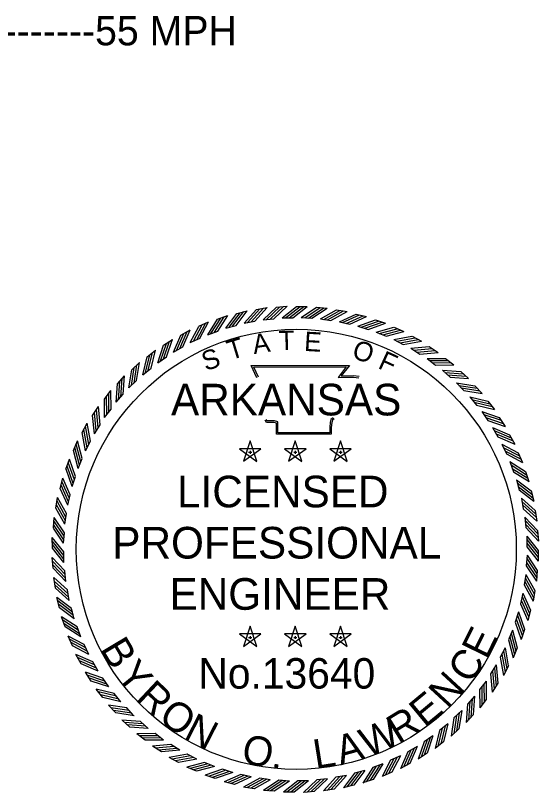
# Model space of a CAD drawing. Extents: x 171 to 3403, y 68 to 2102.
# Drawn here: x 2978.6 to 3245.8, y 313.8 to 710.8 of the extents above; entities that cross this region are included whole.
import ezdxf

# ---------------------------------------------------------------- set-up
doc = ezdxf.new("R2010")
doc.units = 0
for name, color, linetype in [('1', 7, 'Continuous'), ('G-ANNO-NPLT', 7, 'Continuous'), ('STAMP', 7, 'Continuous')]:
    doc.layers.add(name, color=color, linetype=linetype)

msp = doc.modelspace()

# ---------------------------------------------------------------- linework, layer by layer
at = {"layer": 'G-ANNO-NPLT'}
msp.add_circle((3122.09, 438.03), 112.43, dxfattribs=at)
at = {"layer": 'STAMP'}
for p, q in [((3091.74, 558.52), (3097, 559.91)), ((3101.79, 560.58), (3107.15, 561.52)), ((3111.98, 561.8), (3117.4, 562.29)), ((3122.28, 562.1), (3127.72, 562.1)), ((3132.48, 561.69), (3137.9, 561.29)), ((3142.65, 560.37), (3148.03, 559.52)), ((3081.89, 555.65), (3087.02, 557.46)), ((3105.11, 555.35), (3110.54, 555.85)), ((3114.86, 556.31), (3120.31, 556.31)), ((3124.64, 556.46), (3130.08, 556.06)), ((3134.41, 555.8), (3139.8, 554.96)), ((3152.68, 558.21), (3157.97, 556.93)), ((3072.32, 551.97), (3077.28, 554.2)), ((3086.03, 551.03), (3091.3, 552.42)), ((3095.48, 553.59), (3100.85, 554.53)), ((3144.09, 554.34), (3149.39, 553.05)), ((3153.62, 552.09), (3158.8, 550.36)), ((3162.5, 555.24), (3167.66, 553.52)), ((3063.08, 547.51), (3067.84, 550.14)), ((3076.82, 547.71), (3081.96, 549.53)), ((3162.93, 549.05), (3167.94, 546.91)), ((3172.03, 551.46), (3177.04, 549.32)), ((3054.24, 542.3), (3058.77, 545.32)), ((3067.92, 543.64), (3072.89, 545.88)), ((3171.95, 545.26), (3176.78, 542.71)), ((3181.23, 546.91), (3186.04, 544.36)), ((3059.38, 538.85), (3064.15, 541.49)), ((3180.64, 540.74), (3185.23, 537.8)), ((3190.01, 541.61), (3194.6, 538.67)), ((3045.86, 536.38), (3050.12, 539.77)), ((3051.27, 533.36), (3055.81, 536.39)), ((3038, 529.79), (3041.97, 533.52)), ((3188.91, 535.51), (3193.25, 532.2)), ((3198.33, 535.61), (3202.66, 532.3)), ((3043.64, 527.23), (3047.91, 530.62)), ((3196.73, 529.62), (3200.78, 525.96)), ((3206.13, 528.94), (3210.16, 525.29)), ((3030.7, 522.58), (3034.35, 526.61)), ((3036.54, 520.49), (3040.52, 524.22)), ((3204.04, 523.1), (3207.77, 519.12)), ((3213.34, 521.64), (3217.07, 517.67)), ((3024.03, 514.78), (3027.34, 519.11)), ((3030.02, 513.18), (3033.68, 517.23)), ((3210.78, 516), (3214.17, 511.73)), ((3219.93, 513.78), (3223.32, 509.52)), ((3018.03, 506.46), (3020.96, 511.05)), ((3024.13, 505.36), (3027.44, 509.7)), ((3216.91, 508.37), (3219.94, 503.83)), ((3225.85, 505.4), (3228.87, 500.87)), ((3012.73, 497.68), (3015.28, 502.49)), ((3018.9, 497.09), (3021.84, 501.68)), ((3222.4, 500.26), (3225.04, 495.49)), ((3231.06, 496.56), (3233.69, 491.8)), ((3008.18, 488.48), (3010.32, 493.49)), ((3014.38, 488.4), (3016.93, 493.23)), ((3098.5, 493.43), (3095.09, 482.99)), ((3101.89, 482.99), (3098.51, 493.44)), ((3121.58, 493.43), (3118.18, 482.99)), ((3124.98, 482.99), (3121.59, 493.44)), ((3144.67, 493.43), (3141.26, 482.99)), ((3148.06, 482.99), (3144.68, 493.44)), ((3103.99, 489.44), (3093, 489.46)), ((3093.01, 489.44), (3101.89, 482.98)), ((3095.11, 482.99), (3104, 489.44)), ((3127.07, 489.44), (3116.09, 489.46)), ((3116.1, 489.44), (3124.98, 482.98)), ((3118.19, 482.99), (3127.09, 489.44)), ((3150.16, 489.44), (3139.17, 489.46)), ((3139.18, 489.44), (3148.06, 482.98)), ((3141.28, 482.99), (3150.17, 489.44)), ((3227.19, 491.72), (3229.43, 486.75)), ((3010.59, 479.38), (3012.73, 484.39)), ((3097.72, 487.69), (3099.35, 487.69)), ((3098.51, 488.28), (3098.51, 486.9)), ((3120.8, 487.69), (3122.44, 487.69)), ((3121.59, 488.28), (3121.59, 486.9)), ((3143.89, 487.69), (3145.52, 487.69)), ((3144.68, 488.28), (3144.68, 486.9)), ((3235.52, 487.32), (3237.75, 482.36)), ((3004.4, 478.95), (3006.12, 484.11)), ((3231.26, 482.82), (3233.08, 477.68)), ((3239.2, 477.75), (3241.01, 472.62)), ((3001.43, 469.13), (3002.71, 474.42)), ((3007.55, 470.07), (3009.28, 475.25)), ((3234.58, 473.61), (3235.97, 468.33)), ((2999.27, 459.1), (3000.12, 464.48)), ((3005.3, 460.54), (3006.59, 465.84)), ((3242.07, 467.9), (3243.46, 462.64)), ((3237.14, 464.16), (3238.08, 458.79)), ((3244.13, 457.85), (3245.07, 452.49)), ((2997.95, 448.93), (2998.35, 454.35)), ((3003.84, 450.86), (3004.68, 456.25)), ((3238.9, 454.53), (3239.4, 449.1)), ((3003.18, 441.09), (3003.58, 446.53)), ((3239.86, 444.78), (3239.91, 439.33)), ((3245.35, 447.66), (3245.84, 442.24)), ((2997.47, 438.68), (2997.42, 444.12)), ((3003.33, 431.3), (3003.28, 436.76)), ((3245.72, 437.41), (3245.77, 431.97)), ((2997.84, 428.43), (2997.35, 433.85)), ((3240.01, 435), (3239.61, 429.56)), ((3004.29, 421.56), (3003.79, 426.99)), ((3239.35, 425.23), (3238.51, 419.84)), ((3245.24, 427.16), (3244.84, 421.74)), ((2999.06, 418.24), (2998.12, 423.6)), ((3006.05, 411.93), (3005.11, 417.3)), ((3243.92, 416.99), (3243.07, 411.61)), ((3001.12, 408.19), (2999.73, 413.45)), ((3237.89, 415.55), (3236.6, 410.25)), ((3008.61, 402.48), (3007.22, 407.75)), ((3235.64, 406.02), (3233.91, 400.84)), ((3241.76, 406.96), (3240.48, 401.67)), ((3003.99, 398.34), (3002.18, 403.47)), ((3011.93, 393.27), (3010.11, 398.41)), ((3098.5, 398.78), (3095.09, 388.34)), ((3101.89, 388.34), (3098.51, 398.79)), ((3121.58, 398.78), (3118.18, 388.34)), ((3124.98, 388.34), (3121.59, 398.79)), ((3144.67, 398.78), (3141.26, 388.34)), ((3148.06, 388.34), (3144.68, 398.79)), ((3238.79, 397.14), (3237.07, 391.98)), ((3007.67, 388.77), (3005.44, 393.73)), ((3103.99, 394.79), (3093, 394.8)), ((3093.01, 394.79), (3101.89, 388.33)), ((3095.11, 388.34), (3104, 394.79)), ((3097.72, 393.04), (3099.35, 393.04)), ((3098.51, 393.63), (3098.51, 392.25)), ((3127.07, 394.79), (3116.09, 394.8)), ((3116.1, 394.79), (3124.98, 388.33)), ((3118.19, 388.34), (3127.09, 394.79)), ((3120.8, 393.04), (3122.44, 393.04)), ((3121.59, 393.63), (3121.59, 392.25)), ((3150.16, 394.79), (3139.17, 394.8)), ((3139.18, 394.79), (3148.06, 388.33)), ((3141.28, 388.34), (3150.17, 394.79)), ((3143.89, 393.04), (3145.52, 393.04)), ((3144.68, 393.63), (3144.68, 392.25)), ((3232.6, 396.71), (3230.46, 391.7)), ((3016, 384.37), (3013.76, 389.34)), ((3228.81, 387.69), (3226.26, 382.86)), ((3235.01, 387.61), (3232.87, 382.6)), ((3012.13, 379.53), (3009.5, 384.29)), ((3020.79, 375.83), (3018.15, 380.6)), ((3224.29, 379), (3221.35, 374.41)), ((3230.46, 378.41), (3227.91, 373.6)), ((3017.34, 370.69), (3014.32, 375.21)), ((3026.28, 367.72), (3023.25, 372.26)), ((3219.06, 370.72), (3215.75, 366.39)), ((3225.16, 369.63), (3222.22, 365.04)), ((3023.26, 362.31), (3019.87, 366.57)), ((3032.41, 360.09), (3029.02, 364.36)), ((3213.17, 362.91), (3209.51, 358.86)), ((3219.16, 361.31), (3215.85, 356.98)), ((3029.85, 354.45), (3026.12, 358.41)), ((3039.15, 352.99), (3035.42, 356.97)), ((3206.65, 355.6), (3202.67, 351.87)), ((3212.49, 353.51), (3208.84, 349.48)), ((3037.06, 347.15), (3033.03, 350.8)), ((3046.46, 346.47), (3042.41, 350.13)), ((3199.55, 348.86), (3195.28, 345.47)), ((3205.19, 346.3), (3201.22, 342.57)), ((3044.86, 340.48), (3040.53, 343.79)), ((3054.27, 340.58), (3049.94, 343.89)), ((3191.92, 342.73), (3187.38, 339.7)), ((3062.55, 335.35), (3057.96, 338.29)), ((3197.33, 339.71), (3193.07, 336.32)), ((3053.18, 334.48), (3048.59, 337.41)), ((3183.81, 337.24), (3179.04, 334.6)), ((3188.95, 333.79), (3184.42, 330.77)), ((3061.96, 329.18), (3057.15, 331.73)), ((3071.24, 330.83), (3066.41, 333.38)), ((3175.27, 332.45), (3170.3, 330.21)), ((3071.16, 324.63), (3066.15, 326.77)), ((3080.26, 327.04), (3075.25, 329.18)), ((3089.57, 324), (3084.39, 325.72)), ((3166.37, 328.38), (3161.23, 326.56)), ((3180.11, 328.58), (3175.35, 325.95)), ((3080.69, 320.85), (3075.53, 322.57)), ((3099.1, 321.75), (3093.8, 323.04)), ((3147.71, 322.5), (3142.34, 321.56)), ((3157.16, 325.06), (3151.88, 323.67)), ((3170.87, 324.12), (3165.91, 321.89)), ((3090.51, 317.88), (3085.22, 319.16)), ((3108.78, 320.29), (3103.39, 321.13)), ((3118.55, 319.63), (3113.11, 320.03)), ((3128.33, 319.78), (3122.88, 319.73)), ((3138.08, 320.74), (3132.65, 320.24)), ((3161.3, 320.44), (3156.17, 318.63)), ((3100.54, 315.72), (3095.16, 316.57)), ((3110.71, 314.4), (3105.29, 314.8)), ((3120.96, 313.92), (3115.52, 313.87)), ((3131.21, 314.29), (3125.79, 313.79)), ((3141.4, 315.51), (3136.04, 314.57)), ((3151.45, 317.57), (3146.19, 316.18))]:
    msp.add_line(p, q, dxfattribs=at)
for points in [[(3091.3, 552.42), (3097.01, 559.91)], [(3095.48, 553.58), (3101.78, 560.57)], [(3097.2, 553.87), (3103.51, 560.86)], [(3099.06, 554.24), (3105.37, 561.23)], [(3100.85, 554.54), (3107.15, 561.53)], [(3105.11, 555.34), (3111.97, 561.79)], [(3106.85, 555.49), (3113.71, 561.93)], [(3108.73, 555.7), (3115.59, 562.15)], [(3110.54, 555.85), (3117.4, 562.3)], [(3114.85, 556.3), (3122.27, 562.09)], [(3116.6, 556.29), (3124.03, 562.08)], [(3118.49, 556.33), (3125.92, 562.12)], [(3120.3, 556.31), (3127.73, 562.1)], [(3124.64, 556.46), (3132.47, 561.69)], [(3126.38, 556.31), (3134.21, 561.54)], [(3128.27, 556.21), (3136.1, 561.44)], [(3130.08, 556.06), (3137.91, 561.29)], [(3134.41, 555.8), (3142.64, 560.37)], [(3136.13, 555.51), (3144.37, 560.08)], [(3138.01, 555.26), (3146.24, 559.82)], [(3078.47, 548.27), (3083.54, 556.21)], [(3080.24, 548.94), (3085.31, 556.88)], [(3081.96, 549.53), (3087.03, 557.47)], [(3086.02, 551.03), (3091.73, 558.52)], [(3087.72, 551.46), (3093.43, 558.95)], [(3089.54, 551.98), (3095.25, 559.47)], [(3139.8, 554.96), (3148.03, 559.53)], [(3144.09, 554.34), (3152.67, 558.21)], [(3145.78, 553.91), (3154.37, 557.78)], [(3147.63, 553.5), (3156.22, 557.37)], [(3149.39, 553.06), (3157.97, 556.93)], [(3067.91, 543.63), (3072.31, 551.96)], [(3069.52, 544.34), (3073.91, 552.66)], [(3071.22, 545.15), (3075.62, 553.48)], [(3072.88, 545.88), (3077.28, 554.2)], [(3076.82, 547.7), (3081.89, 555.64)], [(3153.61, 552.09), (3162.49, 555.23)], [(3155.27, 551.52), (3164.14, 554.66)], [(3157.08, 550.96), (3165.95, 554.11)], [(3158.79, 550.37), (3167.67, 553.52)], [(3060.92, 539.67), (3064.61, 548.33)], [(3062.55, 540.62), (3066.25, 549.29)], [(3064.15, 541.49), (3067.84, 550.15)], [(3162.92, 549.05), (3172.02, 551.46)], [(3164.52, 548.35), (3173.63, 550.75)], [(3166.28, 547.64), (3175.38, 550.05)], [(3167.94, 546.91), (3177.04, 549.32)], [(3054.28, 535.4), (3057.25, 544.33)], [(3055.8, 536.39), (3058.77, 545.33)], [(3059.38, 538.84), (3063.07, 547.5)], [(3171.95, 545.26), (3181.22, 546.9)], [(3173.49, 544.43), (3182.76, 546.07)], [(3175.18, 543.58), (3184.45, 545.22)], [(3176.77, 542.72), (3186.04, 544.36)], [(3051.27, 533.36), (3054.23, 542.29)], [(3052.73, 534.31), (3055.7, 543.25)], [(3180.63, 540.74), (3190, 541.61)], [(3182.09, 539.78), (3191.47, 540.65)], [(3043.64, 527.22), (3045.85, 536.37)], [(3045.02, 528.3), (3047.24, 537.45)], [(3046.47, 529.51), (3048.69, 538.66)], [(3047.9, 530.62), (3050.12, 539.77)], [(3183.71, 538.79), (3193.09, 539.67)], [(3185.23, 537.8), (3194.6, 538.68)], [(3039.18, 522.99), (3040.63, 532.29)], [(3040.51, 524.22), (3041.97, 533.52)], [(3102.01, 525.67), (3099.1, 531.96), (3149.3, 531.99), (3145.1, 526.72), (3148.51, 526.76), (3151.36, 526.8), (3154.21, 526.49)], [(3188.91, 535.51), (3198.32, 535.61)], [(3190.29, 534.43), (3199.71, 534.53)], [(3191.82, 533.32), (3201.23, 533.42)], [(3193.25, 532.21), (3202.66, 532.3)], [(3036.54, 520.48), (3037.99, 529.78)], [(3037.83, 521.67), (3039.28, 530.97)], [(3102.73, 526.01), (3100.35, 531.16), (3147.65, 531.19), (3143.44, 525.9), (3148.52, 525.97), (3151.32, 526), (3154.12, 525.7)], [(3196.73, 529.62), (3206.12, 528.94)], [(3198.01, 528.43), (3207.41, 527.75)], [(3032.44, 515.89), (3033.13, 525.29)], [(3033.67, 517.23), (3034.35, 526.62)], [(3199.44, 527.2), (3208.84, 526.51)], [(3200.78, 525.97), (3210.17, 525.29)], [(3030.02, 513.17), (3030.7, 522.57)], [(3031.21, 514.46), (3031.89, 523.86)], [(3204.03, 523.1), (3213.33, 521.65)], [(3205.22, 521.81), (3214.52, 520.36)], [(3206.54, 520.46), (3215.84, 519.01)], [(3025.21, 506.74), (3025.11, 516.15)], [(3026.32, 508.27), (3026.22, 517.68)], [(3027.43, 509.7), (3027.34, 519.11)], [(3207.77, 519.13), (3217.07, 517.67)], [(3024.13, 505.36), (3024.03, 514.77)], [(3210.77, 516), (3219.92, 513.79)], [(3211.85, 514.62), (3221, 512.4)], [(3213.06, 513.17), (3222.21, 510.95)], [(3020.85, 500.16), (3019.97, 509.53)], [(3021.84, 501.68), (3020.96, 511.05)], [(3214.17, 511.74), (3223.32, 509.52)], [(3216.91, 508.37), (3225.84, 505.41)], [(3018.9, 497.08), (3018.03, 506.45)], [(3019.86, 498.54), (3018.99, 507.92)], [(3141.39, 504.64), (3140.53, 503.94), (3140.25, 502.9), (3139.96, 500.3), (3139.96, 496.83), (3111.94, 496.83), (3111.94, 501.51), (3111.94, 502.56), (3110.81, 502.9), (3106.82, 502.9), (3106.11, 503.98)], [(3140.89, 505.26), (3139.83, 504.4), (3139.46, 503.05), (3139.17, 500.34), (3139.17, 497.63), (3112.74, 497.63), (3112.74, 501.51), (3112.74, 503.14), (3110.93, 503.7), (3107.25, 503.7), (3106.78, 504.42)], [(3217.86, 506.91), (3226.8, 503.94)], [(3218.95, 505.36), (3227.88, 502.39)], [(3016.06, 491.63), (3014.42, 500.9)], [(3016.92, 493.22), (3015.28, 502.49)], [(3219.94, 503.84), (3228.88, 500.87)], [(3222.39, 500.26), (3231.05, 496.57)], [(3014.38, 488.4), (3012.74, 497.67)], [(3015.21, 489.94), (3013.57, 499.21)], [(3223.22, 498.72), (3231.88, 495.03)], [(3224.17, 497.09), (3232.84, 493.39)], [(3012.72, 484.39), (3010.32, 493.49)], [(3225.04, 495.49), (3233.7, 491.8)], [(3010.59, 479.37), (3008.18, 488.47)], [(3011.29, 480.97), (3008.89, 490.08)], [(3012, 482.73), (3009.59, 491.83)], [(3227.18, 491.73), (3235.51, 487.33)], [(3227.89, 490.12), (3236.21, 485.72)], [(3228.7, 488.42), (3237.03, 484.02)], [(3229.43, 486.75), (3237.75, 482.36)], [(3008.12, 471.72), (3004.97, 480.59)], [(3008.68, 473.53), (3005.53, 482.4)], [(3009.27, 475.24), (3006.12, 484.12)], [(3231.25, 482.82), (3239.19, 477.75)], [(3231.82, 481.17), (3239.76, 476.1)], [(3007.55, 470.06), (3004.41, 478.94)], [(3232.49, 479.4), (3240.43, 474.33)], [(3233.08, 477.68), (3241.02, 472.61)], [(3006.14, 464.08), (3002.27, 472.66)], [(3006.58, 465.84), (3002.71, 474.42)], [(3234.58, 473.61), (3242.07, 467.91)], [(3005.3, 460.54), (3001.43, 469.12)], [(3005.73, 462.23), (3001.86, 470.82)], [(3235.01, 471.92), (3242.5, 466.21)], [(3235.53, 470.1), (3243.02, 464.39)], [(3004.68, 456.25), (3000.11, 464.48)], [(3235.97, 468.34), (3243.46, 462.63)], [(3004.13, 452.58), (2999.56, 460.82)], [(3004.38, 454.46), (2999.81, 462.69)], [(3237.13, 464.16), (3244.12, 457.86)], [(3237.42, 462.44), (3244.41, 456.13)], [(3237.79, 460.58), (3244.78, 454.27)], [(3003.84, 450.85), (2999.27, 459.09)], [(3238.09, 458.79), (3245.08, 452.49)], [(3003.58, 446.53), (2998.34, 454.36)], [(3238.89, 454.53), (3245.34, 447.67)], [(3239.04, 452.79), (3245.48, 445.92)], [(3003.18, 441.09), (2997.95, 448.92)], [(3003.33, 442.83), (2998.1, 450.66)], [(3003.43, 444.72), (2998.2, 452.55)], [(3239.25, 450.91), (3245.7, 444.05)], [(3239.4, 449.1), (3245.85, 442.24)], [(3239.85, 444.79), (3245.71, 437.42)], [(3003.28, 436.75), (2997.42, 444.12)], [(3003.28, 434.94), (2997.42, 442.31)], [(3239.85, 443.04), (3245.71, 435.67)], [(3239.91, 441.15), (3245.77, 433.78)], [(3003.34, 433.05), (2997.48, 440.42)], [(3003.34, 431.3), (2997.48, 438.67)], [(3239.91, 439.34), (3245.77, 431.96)], [(3003.79, 426.99), (2997.34, 433.85)], [(3239.86, 433.26), (3245.09, 425.43)], [(3240.01, 435), (3245.24, 427.17)], [(3003.94, 425.18), (2997.49, 432.04)], [(3004.15, 423.3), (2997.71, 430.16)], [(3239.61, 429.56), (3244.84, 421.73)], [(3239.76, 431.37), (3244.99, 423.54)], [(3004.3, 421.56), (2997.85, 428.42)], [(3239.35, 425.23), (3243.92, 417)], [(3005.1, 417.3), (2998.11, 423.6)], [(3005.4, 415.51), (2998.41, 421.82)], [(3238.81, 421.63), (3243.38, 413.4)], [(3239.06, 423.51), (3243.63, 415.27)], [(3005.77, 413.65), (2998.78, 419.96)], [(3006.06, 411.93), (2999.07, 418.23)], [(3238.51, 419.84), (3243.08, 411.61)], [(3007.22, 407.75), (2999.73, 413.46)], [(3237.46, 413.86), (3241.33, 405.27)], [(3237.89, 415.55), (3241.76, 406.97)], [(3007.66, 405.99), (3000.17, 411.7)], [(3008.18, 404.17), (3000.69, 409.88)], [(3236.61, 410.25), (3240.48, 401.67)], [(3237.05, 412.01), (3240.92, 403.42)], [(3008.61, 402.47), (3001.12, 408.18)], [(3235.64, 406.03), (3238.78, 397.15)], [(3010.11, 398.41), (3002.17, 403.48)], [(3010.7, 396.69), (3002.76, 401.76)], [(3234.51, 402.56), (3237.66, 393.69)], [(3235.07, 404.37), (3238.21, 395.5)], [(3011.37, 394.92), (3003.43, 399.99)], [(3011.94, 393.27), (3004, 398.34)], [(3233.92, 400.85), (3237.07, 391.97)], [(3013.76, 389.33), (3005.44, 393.73)], [(3231.19, 393.36), (3233.6, 384.26)], [(3231.9, 395.11), (3234.3, 386.01)], [(3232.6, 396.72), (3235.01, 387.61)], [(3014.49, 387.67), (3006.16, 392.07)], [(3015.3, 385.97), (3006.98, 390.36)], [(3230.47, 391.7), (3232.87, 382.6)], [(3016.01, 384.36), (3007.68, 388.76)], [(3227.98, 386.15), (3229.62, 376.88)], [(3228.81, 387.69), (3230.45, 378.42)], [(3018.15, 380.6), (3009.49, 384.29)], [(3019.02, 379), (3010.35, 382.7)], [(3226.27, 382.87), (3227.91, 373.6)], [(3227.13, 384.46), (3228.77, 375.19)], [(3019.97, 377.37), (3011.31, 381.06)], [(3020.8, 375.83), (3012.14, 379.52)], [(3223.33, 377.55), (3224.2, 368.17)], [(3224.29, 379.01), (3225.16, 369.64)], [(3023.25, 372.25), (3014.31, 375.22)], [(3024.24, 370.73), (3015.3, 373.7)], [(3221.35, 374.41), (3222.23, 365.04)], [(3222.34, 375.93), (3223.22, 366.55)], [(3025.33, 369.18), (3016.39, 372.15)], [(3026.28, 367.72), (3017.35, 370.68)], [(3217.98, 369.35), (3218.08, 359.93)], [(3219.06, 370.73), (3219.16, 361.32)], [(3029.02, 364.35), (3019.87, 366.57)], [(3215.76, 366.39), (3215.85, 356.98)], [(3216.87, 367.82), (3216.97, 358.41)], [(3030.13, 362.92), (3020.98, 365.14)], [(3031.34, 361.47), (3022.19, 363.69)], [(3032.42, 360.09), (3023.26, 362.3)], [(3211.98, 361.63), (3211.3, 352.23)], [(3213.17, 362.91), (3212.49, 353.52)], [(3035.42, 356.96), (3026.12, 358.42)], [(3209.52, 358.86), (3208.84, 349.47)], [(3210.75, 360.19), (3210.06, 350.8)], [(3036.65, 355.63), (3027.35, 357.08)], [(3037.97, 354.28), (3028.67, 355.73)], [(3039.16, 352.99), (3029.86, 354.44)], [(3205.36, 354.42), (3203.91, 345.12)], [(3206.65, 355.61), (3205.2, 346.31)], [(3042.41, 350.12), (3033.02, 350.8)], [(3043.75, 348.89), (3034.35, 349.58)], [(3202.68, 351.87), (3201.22, 342.57)], [(3204.01, 353.1), (3202.56, 343.8)], [(3045.18, 347.66), (3035.78, 348.34)], [(3046.46, 346.47), (3037.07, 347.15)], [(3195.29, 345.47), (3193.07, 336.32)], [(3196.72, 346.58), (3194.5, 337.43)], [(3198.17, 347.79), (3195.95, 338.64)], [(3199.55, 348.87), (3197.34, 339.71)], [(3049.94, 343.88), (3040.53, 343.79)], [(3051.37, 342.77), (3041.96, 342.67)], [(3052.9, 341.66), (3043.48, 341.56)], [(3190.46, 341.78), (3187.49, 332.84)], [(3191.92, 342.73), (3188.96, 333.8)], [(3054.28, 340.58), (3044.87, 340.48)], [(3057.96, 338.29), (3048.59, 337.41)], [(3187.39, 339.7), (3184.42, 330.76)], [(3188.91, 340.69), (3185.94, 331.75)], [(3059.48, 337.3), (3050.1, 336.42)], [(3061.1, 336.31), (3051.72, 335.44)], [(3062.56, 335.35), (3053.19, 334.48)], [(3179.04, 334.6), (3175.35, 325.94)], [(3180.64, 335.47), (3176.94, 326.8)], [(3182.27, 336.42), (3178.58, 327.76)], [(3183.81, 337.25), (3180.12, 328.59)], [(3066.42, 333.37), (3057.15, 331.73)], [(3068.01, 332.51), (3058.74, 330.87)], [(3069.7, 331.66), (3060.43, 330.02)], [(3071.24, 330.83), (3061.97, 329.18)], [(3170.3, 330.21), (3165.91, 321.89)], [(3171.97, 330.94), (3167.57, 322.61)], [(3173.67, 331.75), (3169.28, 323.43)], [(3175.28, 332.46), (3170.88, 324.13)], [(3075.25, 329.17), (3066.15, 326.77)], [(3076.91, 328.45), (3067.81, 326.04)], [(3078.67, 327.74), (3069.56, 325.34)], [(3080.27, 327.04), (3071.16, 324.63)], [(3084.4, 325.72), (3075.52, 322.57)], [(3161.23, 326.56), (3156.16, 318.62)], [(3162.95, 327.15), (3157.88, 319.21)], [(3164.72, 327.82), (3159.65, 319.88)], [(3166.37, 328.39), (3161.3, 320.45)], [(3086.11, 325.13), (3077.24, 321.98)], [(3087.92, 324.57), (3079.05, 321.42)], [(3089.58, 324), (3080.7, 320.86)], [(3093.8, 323.03), (3085.22, 319.16)], [(3095.56, 322.59), (3086.97, 318.72)], [(3097.41, 322.18), (3088.82, 318.31)], [(3099.1, 321.75), (3090.52, 317.88)], [(3144.13, 321.85), (3137.82, 314.86)], [(3145.99, 322.22), (3139.68, 315.23)], [(3147.71, 322.51), (3141.41, 315.52)], [(3151.89, 323.67), (3146.18, 316.18)], [(3153.65, 324.11), (3147.94, 316.62)], [(3155.47, 324.63), (3149.76, 317.14)], [(3157.17, 325.06), (3151.46, 317.57)], [(3103.39, 321.13), (3095.16, 316.56)], [(3105.18, 320.83), (3096.95, 316.26)], [(3107.06, 320.58), (3098.82, 316.01)], [(3108.78, 320.29), (3100.55, 315.72)], [(3113.11, 320.03), (3105.28, 314.79)], [(3114.92, 319.88), (3107.09, 314.65)], [(3116.81, 319.78), (3108.98, 314.55)], [(3118.55, 319.63), (3110.72, 314.4)], [(3122.89, 319.73), (3115.51, 313.87)], [(3124.7, 319.73), (3117.33, 313.87)], [(3126.59, 319.79), (3119.22, 313.93)], [(3128.34, 319.79), (3120.97, 313.93)], [(3132.65, 320.24), (3125.79, 313.79)], [(3134.46, 320.39), (3127.6, 313.94)], [(3136.34, 320.6), (3129.48, 314.16)], [(3138.08, 320.75), (3131.22, 314.3)], [(3142.34, 321.55), (3136.04, 314.56)]]:
    msp.add_lwpolyline(points, dxfattribs=at)

# ---------------------------------------------------------------- texts
at = {"layer": '1'}
msp.add_text('DESIGN SPEED----------------55 MPH', height=15, dxfattribs=at).set_placement((2761.91, 695.55))
at = {"layer": 'STAMP'}
for s, height, rotation, p in [('A', 9.9, 8.6788, (3100.47, 537.76)), ('T', 9.9, 1.4789, (3113.26, 539.73)), ('E', 9.9, 356.672, (3125.93, 539.43)), ('T', 9.9, 16.9015, (3088.45, 534.62)), ('O', 9.9, 341.2218, (3149.97, 536.03)), ('S', 9.9, 19.7726, (3075.86, 528.97)), ('F', 9.9, 335.3628, (3163.32, 530.81)), ('E', 15.04, 63.7362, (3219.49, 381.2)), ('B', 15.04, 300.7985, (3021.49, 387.21)), ('C', 15.04, 56.0754, (3211.05, 368.73)), ('Y', 15.04, 308.8241, (3029.57, 373.66)), ('N', 15.04, 47.3202, (3199.46, 356)), ('R', 15.04, 316.8497, (3039.46, 361.37)), ('E', 15.04, 39.6594, (3187.84, 346.42)), ('O', 15.04, 324.8753, (3050.97, 350.58)), ('N', 15.04, 332.9009, (3063.88, 341.5)), ('R', 15.04, 31.6338, (3174.4, 338.14)), ('W', 15.04, 22.8786, (3158.59, 331.35)), ('O', 15.04, 349.3169, (3093.53, 328.97)), ('A', 15.04, 15.5826, (3144.75, 327.58)), ('L', 15.04, 9.0162, (3131.97, 325.72)), ('.', 15.04, 357.3425, (3109.04, 326.05))]:
    msp.add_text(s, height=height, rotation=rotation, dxfattribs=at).set_placement(p)
for s, height, p in [('ARKANSAS', 16.159, (3058.07, 506.45)), ('LICENSED', 16.159, (3061.15, 459.48)), ('PROFESSIONAL', 16.1592, (3028.06, 433.32)), ('ENGINEER', 16.159, (3057.3, 407.15)), ('No.13640', 15.582, (3072.08, 366.86))]:
    msp.add_text(s, height=height, dxfattribs=at).set_placement(p)

doc.saveas('drawing.dxf')
